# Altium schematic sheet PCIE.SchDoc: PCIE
size A3; Author: Silvio Navaretti; CompanyName: ARDUINO; Organization: ARDUINO; SheetNumber: 24; SheetTotal: 51; RevAuthor: Silvio Navaretti
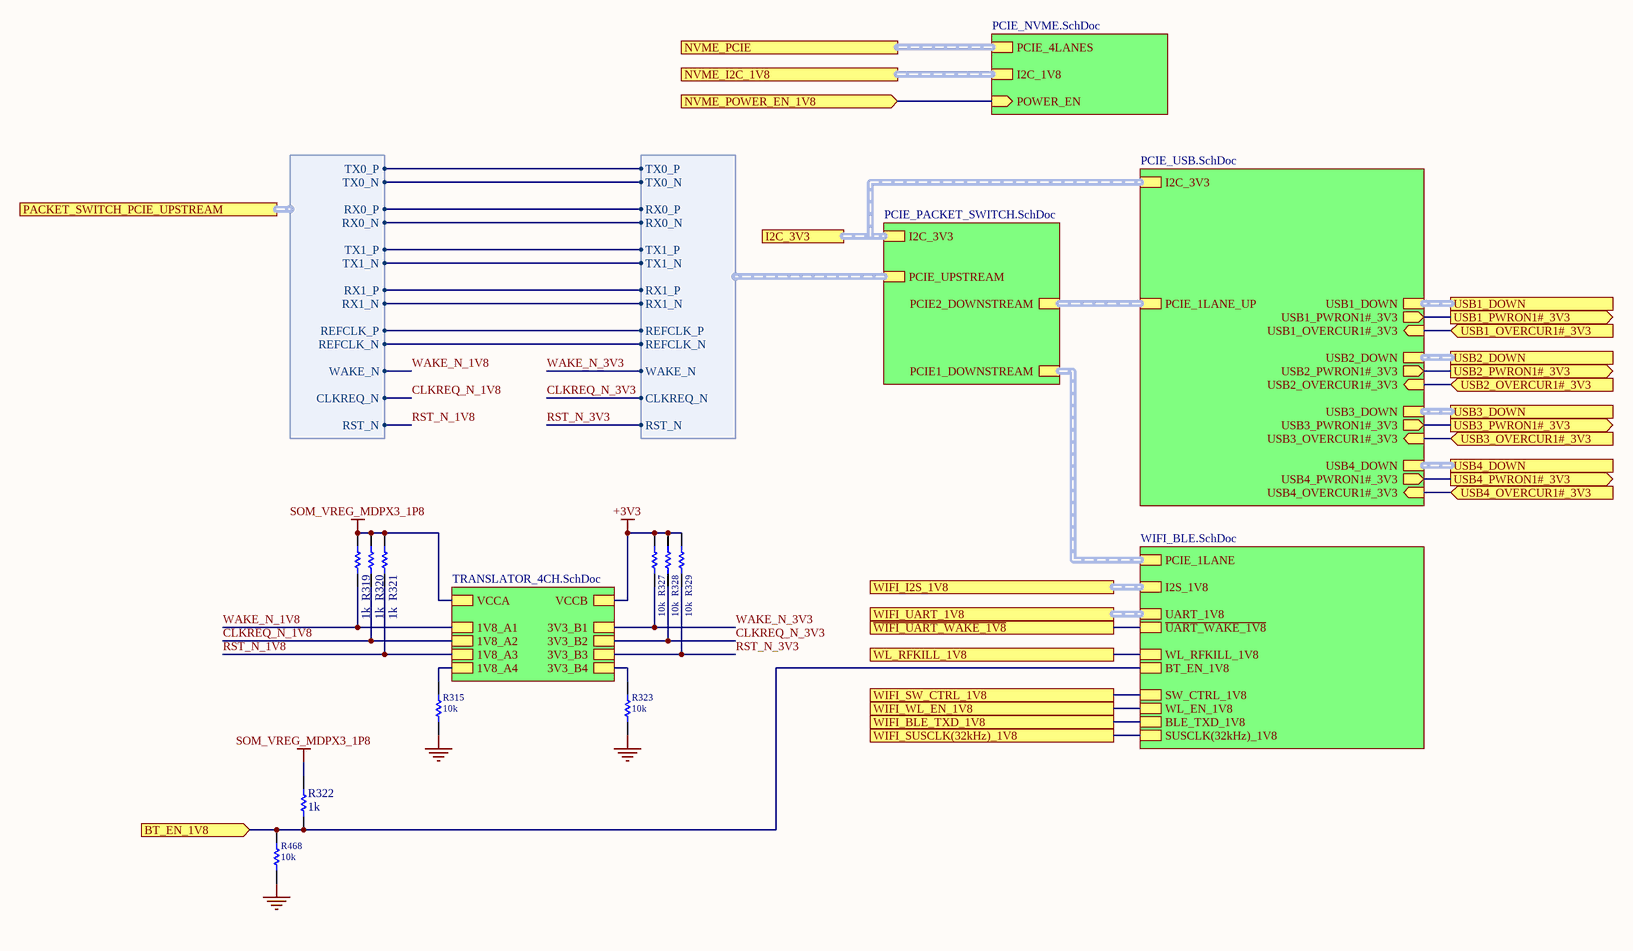
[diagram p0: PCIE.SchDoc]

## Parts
R315  value 10k  [RES-0201]  (hidden comment: RC0201FR-0710KL)
R319  value 1k  [RES-0201]  (hidden comment: RC0201FR-071KL)
R320  value 1k  [RES-0201]  (hidden comment: RC0201FR-071KL)
R321  value 1k  [RES-0201]  (hidden comment: RC0201FR-071KL)
R322  value 1k  [RES-0201]  (hidden comment: RC0201FR-071KL)
R323  value 10k  [RES-0201]  (hidden comment: RC0201FR-0710KL)
R327  value 10k  [RES-0201]  (hidden comment: RC0201FR-0710KL)
R328  value 10k  [RES-0201]  (hidden comment: RC0201FR-0710KL)
R329  value 10k  [RES-0201]  (hidden comment: RC0201FR-0710KL)
R468  value 10k  [RES-0201]  (hidden comment: RC0201FR-0710KL)

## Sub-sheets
U_PCIE_NVME = PCIE_NVME.SchDoc: POWER_EN (in), PCIE_4LANES (harness SOM_MD_PCIE1), I2C_1V8 (harness I2C)
U_PCIE_PACKET_SWITCH = PCIE_PACKET_SWITCH.SchDoc: PCIE_UPSTREAM (harness SOM_MD_PCIE0), I2C_3V3 (harness I2C), PCIE1_DOWNSTREAM (harness PCIE_1LANE), PCIE2_DOWNSTREAM (harness PCIE_1LANE)
U_PCIE_USB = PCIE_USB.SchDoc: USB1_DOWN (harness SOM_MD_USB0), USB1_PWRON1#_3V3 (out), USB1_OVERCUR1#_3V3 (in), USB2_DOWN (harness SOM_MD_USB0), USB2_PWRON1#_3V3 (out), USB2_OVERCUR1#_3V3 (in), USB3_DOWN (harness SOM_MD_USB0), USB3_PWRON1#_3V3 (out), USB3_OVERCUR1#_3V3 (in), USB4_DOWN (harness SOM_MD_USB0), USB4_PWRON1#_3V3 (out), USB4_OVERCUR1#_3V3 (in), PCIE_1LANE_UP (harness PCIE_1LANE), I2C_3V3 (harness I2C)
U_TRANSLATOR_4CH = TRANSLATOR_4CH.SchDoc: 1V8_A1, 1V8_A2, 1V8_A3, 1V8_A4, 3V3_B1, 3V3_B2, 3V3_B3, 3V3_B4, VCCA, VCCB
U_WIFI_BLE = WIFI_BLE.SchDoc: PCIE_1LANE (harness PCIE_1LANE), I2S_1V8 (harness SOM_MD_I2S), WL_RFKILL_1V8, UART_1V8 (harness SOM_MD_UART_FLCRTL), ~{UART_WAKE_1V8}, SW_CTRL_1V8, WL_EN_1V8, BLE_TXD_1V8, SUSCLK(32kHz)_1V8, BT_EN_1V8

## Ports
BT_EN_1V8 (in), I2C_3V3, NVME_I2C_1V8, NVME_PCIE, NVME_POWER_EN_1V8 (in), PACKET_SWITCH_PCIE_UPSTREAM (harness SOM_MD_PCIE0), USB1_DOWN, USB1_OVERCUR1#_3V3 (in), USB1_PWRON1#_3V3 (out), USB2_DOWN, USB2_OVERCUR1#_3V3 (in), USB2_PWRON1#_3V3 (out), USB3_DOWN (harness SOM_MD_USB0), USB3_OVERCUR1#_3V3 (in), USB3_PWRON1#_3V3 (out), USB4_DOWN, USB4_OVERCUR1#_3V3 (in), USB4_PWRON1#_3V3 (out), WIFI_BLE_TXD_1V8, WIFI_I2S_1V8, WIFI_SUSCLK(32kHz)_1V8, WIFI_SW_CTRL_1V8, WIFI_UART_1V8, WIFI_WL_EN_1V8, WL_RFKILL_1V8, ~{WIFI_UART_WAKE_1V8}

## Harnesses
SOM_MD_PCIE0: RX0_N, RX0_P, TX0_P, TX0_N, RX1_N, RX1_P, TX1_P, TX1_N, REFCLK_N, REFCLK_P, WAKE_N, CLKREQ_N, RST_N

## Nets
+3V3: R327.1 R328.1 R329.1 ; sheet U_TRANSLATOR_4CH/VCCB
GND: R315.1 R323.1 R468.1
SOM_VREG_MDPX3_1P8: R319.1 R320.1 R321.1 R322.2 ; sheet U_TRANSLATOR_4CH/VCCA
BT_EN_1V8: R322.1 R468.2 ; port BT_EN_1V8, sheet U_WIFI_BLE/BT_EN_1V8
CLKREQ_N_1V8: R320.2 ; sheet U_TRANSLATOR_4CH/1V8_A2, port PACKET_SWITCH_PCIE_UPSTREAM.CLKREQ_N
CLKREQ_N_3V3: R328.2 ; sheet U_TRANSLATOR_4CH/3V3_B2, sheet U_PCIE_PACKET_SWITCH/PCIE_UPSTREAM.CLKREQ_N
NVME_POWER_EN_1V8: port NVME_POWER_EN_1V8, sheet U_PCIE_NVME/POWER_EN
RST_N_1V8: R321.2 ; sheet U_TRANSLATOR_4CH/1V8_A3, port PACKET_SWITCH_PCIE_UPSTREAM.RST_N
RST_N_3V3: R329.2 ; sheet U_TRANSLATOR_4CH/3V3_B3, sheet U_PCIE_PACKET_SWITCH/PCIE_UPSTREAM.RST_N
USB1_OVERCUR1#_3V3: port USB1_OVERCUR1#_3V3, sheet U_PCIE_USB/USB1_OVERCUR1#_3V3
USB1_PWRON1#_3V3: port USB1_PWRON1#_3V3, sheet U_PCIE_USB/USB1_PWRON1#_3V3
USB2_OVERCUR1#_3V3: port USB2_OVERCUR1#_3V3, sheet U_PCIE_USB/USB2_OVERCUR1#_3V3
USB2_PWRON1#_3V3: port USB2_PWRON1#_3V3, sheet U_PCIE_USB/USB2_PWRON1#_3V3
USB3_OVERCUR1#_3V3: port USB3_OVERCUR1#_3V3, sheet U_PCIE_USB/USB3_OVERCUR1#_3V3
USB3_PWRON1#_3V3: port USB3_PWRON1#_3V3, sheet U_PCIE_USB/USB3_PWRON1#_3V3
USB4_OVERCUR1#_3V3: port USB4_OVERCUR1#_3V3, sheet U_PCIE_USB/USB4_OVERCUR1#_3V3
USB4_PWRON1#_3V3: port USB4_PWRON1#_3V3, sheet U_PCIE_USB/USB4_PWRON1#_3V3
~{WIFI_UART_WAKE_1V8}: port ~{WIFI_UART_WAKE_1V8}, sheet U_WIFI_BLE/~{UART_WAKE_1V8}
WAKE_N_1V8: R319.2 ; sheet U_TRANSLATOR_4CH/1V8_A1, port PACKET_SWITCH_PCIE_UPSTREAM.WAKE_N
WAKE_N_3V3: R327.2 ; sheet U_TRANSLATOR_4CH/3V3_B1, sheet U_PCIE_PACKET_SWITCH/PCIE_UPSTREAM.WAKE_N
WIFI_BLE_TXD_1V8: port WIFI_BLE_TXD_1V8, sheet U_WIFI_BLE/BLE_TXD_1V8
WIFI_SUSCLK(32kHz)_1V8: port WIFI_SUSCLK(32kHz)_1V8, sheet U_WIFI_BLE/SUSCLK(32kHz)_1V8
WIFI_SW_CTRL_1V8: port WIFI_SW_CTRL_1V8, sheet U_WIFI_BLE/SW_CTRL_1V8
WIFI_WL_EN_1V8: port WIFI_WL_EN_1V8, sheet U_WIFI_BLE/WL_EN_1V8
WL_RFKILL_1V8: port WL_RFKILL_1V8, sheet U_WIFI_BLE/WL_RFKILL_1V8
NetR315_2: R315.2 ; sheet U_TRANSLATOR_4CH/1V8_A4
NetR323_2: R323.2 ; sheet U_TRANSLATOR_4CH/3V3_B4
(unnamed): port PACKET_SWITCH_PCIE_UPSTREAM.RX0_N, sheet U_PCIE_PACKET_SWITCH/PCIE_UPSTREAM.RX0_N
(unnamed): port PACKET_SWITCH_PCIE_UPSTREAM.RX0_P, sheet U_PCIE_PACKET_SWITCH/PCIE_UPSTREAM.RX0_P  [a separate net that carries the same name]
(unnamed): port PACKET_SWITCH_PCIE_UPSTREAM.TX0_P, sheet U_PCIE_PACKET_SWITCH/PCIE_UPSTREAM.TX0_P  [a separate net that carries the same name]
(unnamed): port PACKET_SWITCH_PCIE_UPSTREAM.TX0_N, sheet U_PCIE_PACKET_SWITCH/PCIE_UPSTREAM.TX0_N  [a separate net that carries the same name]
(unnamed): port PACKET_SWITCH_PCIE_UPSTREAM.RX1_N, sheet U_PCIE_PACKET_SWITCH/PCIE_UPSTREAM.RX1_N  [a separate net that carries the same name]
(unnamed): port PACKET_SWITCH_PCIE_UPSTREAM.RX1_P, sheet U_PCIE_PACKET_SWITCH/PCIE_UPSTREAM.RX1_P  [a separate net that carries the same name]
(unnamed): port PACKET_SWITCH_PCIE_UPSTREAM.TX1_P, sheet U_PCIE_PACKET_SWITCH/PCIE_UPSTREAM.TX1_P  [a separate net that carries the same name]
(unnamed): port PACKET_SWITCH_PCIE_UPSTREAM.TX1_N, sheet U_PCIE_PACKET_SWITCH/PCIE_UPSTREAM.TX1_N  [a separate net that carries the same name]
(unnamed): port PACKET_SWITCH_PCIE_UPSTREAM.REFCLK_N, sheet U_PCIE_PACKET_SWITCH/PCIE_UPSTREAM.REFCLK_N  [a separate net that carries the same name]
(unnamed): port PACKET_SWITCH_PCIE_UPSTREAM.REFCLK_P, sheet U_PCIE_PACKET_SWITCH/PCIE_UPSTREAM.REFCLK_P  [a separate net that carries the same name]

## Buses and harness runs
harness port I2C_3V3 = sheet U_PCIE_PACKET_SWITCH/I2C_3V3 = sheet U_PCIE_USB/I2C_3V3
harness port NVME_I2C_1V8 = sheet U_PCIE_NVME/I2C_1V8
harness port NVME_PCIE = sheet U_PCIE_NVME/PCIE_4LANES
harness port USB1_DOWN = sheet U_PCIE_USB/USB1_DOWN
harness port USB2_DOWN = sheet U_PCIE_USB/USB2_DOWN
harness port USB3_DOWN = sheet U_PCIE_USB/USB3_DOWN
harness port USB4_DOWN = sheet U_PCIE_USB/USB4_DOWN
harness port WIFI_I2S_1V8 = sheet U_WIFI_BLE/I2S_1V8
harness port WIFI_UART_1V8 = sheet U_WIFI_BLE/UART_1V8
harness sheet U_PCIE_PACKET_SWITCH/PCIE1_DOWNSTREAM = sheet U_WIFI_BLE/PCIE_1LANE
harness sheet U_PCIE_PACKET_SWITCH/PCIE2_DOWNSTREAM = sheet U_PCIE_USB/PCIE_1LANE_UP

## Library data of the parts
R315 R323 R327-R329 R468 = R0145-A.21: RES CHIP 0201 10k 1% 1/20W; Manufacturer: Yageo; Power: 50mW; Temperature coefficient: 200ppm; Code Arduino: R0145
R319-R322 = R0195-A.22: RES CHIP 0201 1k 1% 1/20W; Manufacturer: Yageo; Power: 50mW; Temperature coefficient: 200ppm; Code Arduino: R0195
